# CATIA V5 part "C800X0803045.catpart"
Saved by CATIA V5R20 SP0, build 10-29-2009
Part number: C800X0803045
Source: Unknown
Property "A": "50"
Property "ARTICLENO": "C800X0803045"
Property "B": "23"
Property "BOMINFO": "C800X0803045"
Property "C": "91"
Property "CA": "C800X0803045"
Property "D1": "90"
Property "DES": "ROTATING EYEBOLT WITH RING Ton 8,0 M30x45"
Property "E": "86"
Property "H": "200"
Property "L": "45"
Property "LINA": "C800X0803045"
Property "NB": "C800X0803045"
Property "NBSYN": "$CODE."
Property "NN": "C800X"
Property "NT": "Rotating eyebolt with ring"
Property "SIZE": "M30"
Property "SUPPLIER": "CF"
Property "SW": "80"
Property "WEIGHT": "4400"
Property "WLL": "8.00"
Bounding box of the stored display mesh (mm): x -47.825 to 48, y -45 to 222.825, z -45 to 45
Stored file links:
  C:\Users\Utente\Desktop\3D files 800X\C800X0803045.catpart

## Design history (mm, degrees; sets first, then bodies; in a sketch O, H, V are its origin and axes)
Body1 "Geometry.1" (main body)
  Solid1 "C800X0803045.catpart": solid without history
